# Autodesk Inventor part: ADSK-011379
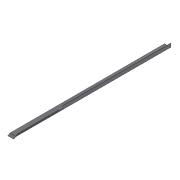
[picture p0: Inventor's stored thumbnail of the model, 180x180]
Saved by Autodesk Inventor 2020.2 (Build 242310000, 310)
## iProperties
Created: 1999-12
Part Number: ADSK-011379
Material: 1.0312 DC05
Document SubType Name: Tôlerie
Designer: sspink
Density: 1 g/cm^3
Sheet Metal Rule: Stahlblech 1.0312 - DC05 -   3.0 mm
Appearance: Metal-Steel(Polish)
Mass: 441.389 g
Surface Area: 3043.15 cm^2
Volume: 441.389 cm^3
Flat Pattern Width: 9.62858 cm
Flat Pattern Length: 155.105 cm
Flat Pattern Area: 1493.44 cm^2
Sheet Metal Width: 96,286 mm
Sheet Metal Length: 1551,047 mm
Sheet Metal Area: 149343,821 mm^2
Control State: 0
Master: False
Checked Out: False
Shininess: 57.0
Length Units: 11269
Angle Units: 11279
Time Units: 11290
Mass Units: 11283
Length Display Precision: 3
Angle Display Precision: 2
Compacted: True
Cutlength: 3.81 X 61.03 (233 SI)
Material Desc: SHEET,S/S, 11 GA
Material_number: A084638
G_L: 96,3x1551 mm
Thickness: 3,000 mm
Dimensions: 50,1x1548,7x75,6 mm
Mass: 0,441 kg
Semi finished: Stahlblech 1.0312 - DC05 -   3.0 mm
VLT_Material: 1.0312 DC05
Density: 8.03
Volumn: 482.19162532114115
Area: 3142.465429778671
PropertySet Name: Model Information
Author: sspink
Revision Number: -
Title: ADSK-011379
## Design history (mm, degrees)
node "Solide1"
  node "Konturlasche1"
  node "Lasche1"
  node "Lasche2"
sketch "Sketch1"
  geometry: L1 (0, 38)-(0, 0); L2 (0, 0)-(-63.5, 0) reference; 1 further point
  constraints: 4 end point, 1 coincident, 1 horizontal, 1 perpendicular
  dimensions: "d70" = 38 distance of L1.start L1.end; "d72" = 63.5 distance of L1.end L2.end
feature "Ecke1" dims "d79" = 3, "d80" = 12 (= CornerReliefSize), "d81" = 3 (= TailleJeu), "d82" = 3 (= TailleRayonJacobi)
sketch "Skizze12"
  geometry: L1 through (-28.75, 0) direction (1, -6.15e-18); L2 through (0, 12.5) direction (-1.27e-16, 1); L3 (0, 25)-(-57.5, 25); L4 (-57.5, 25)-(-57.5, 0)
  constraints: 6 end point, 1 horizontal, 1 perpendicular, 1 vertical
feature "Grobblech2" dims "d69" = 3 (= Thickness), "d83" = 3 (= BendReliefWidth), "d84" = 1.5 (= BendReliefDepth), "d85" = 6 (= MinimumRemnant), "d86" = 3 (= TransitionRadius), "d87" = 25, "d88" = 30 deg, "d89" = 3 (= BendRadius), "d90" = 12 (= CornerReliefSize), "d91" = 3 (= TailleJeu), "d92" = 3 (= TailleRayonJacobi), "SeamGap" = 0.00508
feature "Biegung5" dims "d69" = 3 (= Thickness), "d83" = 3 (= BendReliefWidth), "d84" = 1.5 (= BendReliefDepth), "d85" = 6 (= MinimumRemnant), "d86" = 3 (= TransitionRadius), "d87" = 25, "d88" = 30 deg, "d89" = 3 (= BendRadius), "SeamGap" = 0.00508
feature "Ecke2" dims "d87" = 25, "d88" = 30 deg, "d90" = 12 (= CornerReliefSize), "d91" = 3 (= TailleJeu), "d92" = 3 (= TailleRayonJacobi)
sketch "Skizze13"
  geometry: L1 (0, 0)-(1527, 0) reference; L2 (460, 0)-(460, -25); L3 (460, -25)-(0, -25); L4 (0, -32)-(0, 0) reference; L5 (1527, 0)-(1527, -32) reference; 1 further point
  constraints: 4 end point, 2 point on line, 1 perpendicular, 1 vertical
  dimensions: "d94" = 460 distance of L2.end L3.end; "d95" = 25 distance of L2.start L2.end
feature "Ausklinkung1" dims "d96" = 3 (= Thickness), "d97" = 0
sketch "Skizze14"
  geometry: L1 through (0, -203) direction (1.52e-16, 1); L2 through (-12.5, 0) direction (-1, 0); L3 (-25, 0)-(-25, -406); L4 (-25, -406)-(0, -406)
  constraints: 6 end point, 1 horizontal, 1 perpendicular, 1 vertical
feature "Grobblech3" dims "d69" = 3 (= Thickness), "d98" = 3 (= BendReliefWidth), "d99" = 1.5 (= BendReliefDepth), "d100" = 6 (= MinimumRemnant), "d101" = 3 (= TransitionRadius), "d102" = 406, "d103" = 0, "d104" = 25, "d105" = 30 deg, "d106" = 3 (= BendRadius), "d107" = 12 (= CornerReliefSize), "d108" = 3 (= TailleJeu), "d109" = 3 (= TailleRayonJacobi), "SeamGap" = 0.00508
feature "Biegung6" dims "d69" = 3 (= Thickness), "d98" = 3 (= BendReliefWidth), "d99" = 1.5 (= BendReliefDepth), "d100" = 6 (= MinimumRemnant), "d101" = 3 (= TransitionRadius), "d104" = 25, "d105" = 30 deg, "d106" = 3 (= BendRadius), "SeamGap" = 0.00508
feature "Ecke3" dims "d104" = 25, "d105" = 30 deg, "d107" = 12 (= CornerReliefSize), "d108" = 3 (= TailleJeu), "d109" = 3 (= TailleRayonJacobi)
feature "Grobblech1" dims "d69" = 3 (= Thickness), "d73" = 3 (= BendReliefWidth), "d74" = 1.5 (= BendReliefDepth), "d75" = 6 (= MinimumRemnant), "d76" = 3 (= TransitionRadius), "d77" = 1527, "d78" = 3 (= BendRadius), "d79" = 3, "d80" = 12 (= CornerReliefSize), "d81" = 3 (= TailleJeu), "d82" = 3 (= TailleRayonJacobi), "SeamGap" = 0.00508
feature "Biegung4" dims "d69" = 3 (= Thickness), "d73" = 3 (= BendReliefWidth), "d74" = 1.5 (= BendReliefDepth), "d75" = 6 (= MinimumRemnant), "d76" = 3 (= TransitionRadius), "d78" = 3 (= BendRadius), "d79" = 3, "SeamGap" = 0.00508
node "Corps solides"
node "Corps surfaciques"
feature "Definition1"
other parameters: "Thickness" = 3 (derived), "BendRadius" = 3 (= Thickness), "BendReliefWidth" = 3 (= Thickness), "BendReliefDepth" = 1.5 (= 0.5 x Thickness), "CornerReliefSize" = 12 (= 4 x Thickness), "MinimumRemnant" = 6 (= 2 x Thickness), "TransitionRadius" = 3 (= BendRadius), "TailleRayonJacobi" = 3 (= BendRadius), "TailleJeu" = 3 (= Thickness), "BendRadius" = 3, "BendReliefDepth" = 1.5, "BendReliefWidth" = 3, "CornerReliefSize" = 12, "MinimumRemnant" = 6, "TailleJeu" = 3, "TailleRayonJacobi" = 3, "Thickness" = 3, "TransitionRadius" = 3
